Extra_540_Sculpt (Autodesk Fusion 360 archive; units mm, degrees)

design "Extra_540_Sculpt" references "Extra_540_freeform v17_Wings_freestyle", "Extra_540_rear_tags"
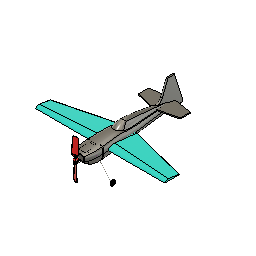
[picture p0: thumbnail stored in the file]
canvas "Canvas1"
canvas "Canvas2"
canvas "Canvas3"
component_insert "Component Insert5"
ground "Ground4"
form "Form2"
sketch "Sketch1" plane through (0, 0, 0) normal (1, 0, 0) x axis (0, 0, -1)
extrude "Extrude1" add sketch "Sketch1" distance 1.5
fillet "Fillet1" radius 1.5
fillet "Fillet2" radius 0.75
form "Form1"
component_insert "Component Insert6"
ground "Ground5"
place_component sketch "Sketch1"
work_plane "WorkPlane1" sketch "Sketch1" AlongDistance 6
sketch "Sketch1" plane through (0, 6, 0) normal (0, 1, 0) x axis (1, 0, 0)
extrude "Extrude1" new body sketch "Sketch1" along normal blind 2
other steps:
create_component "CreateComponent5"
create_component "CreateComponent7"
create_component "CreateComponent8" sketch "Sketch1"

design "Extra_540_freeform_Undercarriage"
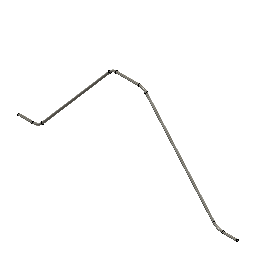
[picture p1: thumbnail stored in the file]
base_feature "Base Feature"
sketch "Path (1)" plane through (0, 0, -48.1) normal (0, 0, 1) x axis (1, 0, 0)
  dimension "d165" = 5
  dimension "d166" = 4
  dimension "d178" = 0
  dimension "d179" = 0
  dimension "d180" = 0
  dimension "d181" = 0
  dimension "d190" = 0
  dimension "d191" = 0
  dimension "d192" = 0
  dimension "d193" = 0
sketch "Profile" plane through (0, 0, 0) normal (1, 0, 0) x axis (0, 0, -1)
  circle C1 centre (47.7, -10.2807) radius 0.375
  dimension "d167" diameter C1 = 0.75
sweep "Sweep1" sketch "Profile" TwistAngle 0 TaperAngle 0

design "Propeller_3_x_1"
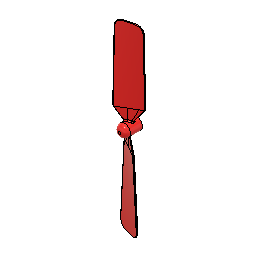
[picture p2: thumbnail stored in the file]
sketch "Sketch1" plane through (0, 0, 0) normal (1, 0, 0) x axis (0, 0, -1)
  dimension "d1" = 1
  dimension "d2" = 2.5
  dimension "d3" = 2
  dimension "d5" = 7
  dimension "d6" = 115
  dimension "d7" = 1.5
revolve "Revolve1" sketch "Sketch1" AlongAngle 360
work_plane "WorkPlane1" AlongDistance 38
sketch "Sketch2" plane through (0, 38, 0) normal (0, 1, 0) x axis (1, 0, 0)
  dimension "d10" = 3
  dimension "d11" = 10
  dimension "d12" = 0.5
  dimension "d13" = 10
work_plane "WorkPlane2" AlongDistance 7
sketch "Sketch3" plane through (0, 7, 0) normal (0, 1, 0) x axis (1, 0, 0)
  dimension "d15" = 10
  dimension "d16" = 0.5
  dimension "d17" = 30
sketch "Sketch4" plane through (0, 0, 0) normal (1, 0, 0) x axis (0, 0, -1)
sweep "Sweep1" sketch "Sketch3" TwistAngle -15 TaperAngle 0
sketch "Sketch5" plane through (0, 0, 0) normal (0, 1, 0) x axis (1, 0, 0)
  dimension "d24" = 0.5
  dimension "d25" = 1
  dimension "d26" = 60
sketch "Sketch6" plane through (0, 0, 0) normal (1, 0, 0) x axis (0, 0, -1)
loft "Loft2" sketch "Sketch5" + "Sketch3"
fillet "Fillet2" radius 3
fillet "Fillet3" radius 2
fillet "Fillet4" radius 0.2
fillet "Fillet5" radius 0.5
circular_pattern "C-Pattern1" TotalAngle 360

design "Extra_540_rear_tags" references "Extra_540_freeform_Undercarriage", "Motor_prop_rear_tags", "Sleeve", "Extra_540_wheel"
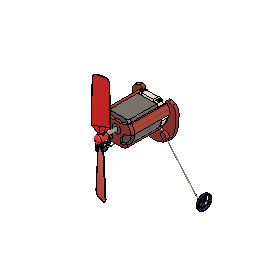
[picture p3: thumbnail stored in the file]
canvas "Canvas1"
canvas "Canvas2"
canvas "Canvas3"
component_insert "Component Insert4"
position "Position2"
base_feature "Base Feature"
work_plane "WorkPlane1" AlongDistance -50.1
sketch "Sketch3" plane through (0, 0, -50.1) normal (0, 0, 1) x axis (1, 0, 0)
extrude "Extrude1" new body sketch "Sketch3" along normal blind 2 taper -5
sketch "Sketch12" plane through (0, 0, -48.1) normal (0, 0, 1) x axis (1, 0, 0)
extrude "Extrude9" cut sketch "Sketch12" no distance stored
sketch "Sketch13" plane through (0, 0, -48.1) normal (0, 0, 1) x axis (1, 0, 0)
  dimension "d100" = 2
  dimension "d104" = 1.5
  dimension "d105" = 6
  dimension "d106" = 12
extrude "Extrude10" add sketch "Sketch13" along normal blind 25
sketch "Sketch14" plane through (0, 0, -23.1) normal (0, 0, 1) x axis (1, 0, 0)
  dimension "d109" = 6.0836
  dimension "d110" = 10
extrude "Extrude11" add sketch "Sketch14" along normal blind 1.5
sketch "Sketch7" plane through (0, 0, -48.1) normal (0, 0, 1) x axis (1, 0, 0)
  dimension "d141" = 4
  dimension "d143" = 4
  dimension "d144" = 2.5
  dimension "d113" = 2
  dimension "d114" = 8
extrude "Extrude5" add sketch "Sketch7" along normal blind 2.5
fillet "Fillet2" radius 1
sketch "Sketch8" plane through (4.0871, 0, 0) normal (1, 0, 0) x axis (0, 0, -1)
sketch "Sketch9" plane through (4.0871, 0, 0) normal (1, 0, 0) x axis (0, 0, -1)
  dimension "d148" = 0.4
  dimension "d149" = 0.8
extrude "Extrude6" cut sketch "Sketch9" to an object
sketch "Sketch10" plane through (0, 0, -48.1) normal (0, 0, 1) x axis (1, 0, 0)
  dimension "d154" = 29.9506
  dimension "d155" = 26.0609
  dimension "d161" = 2.5
  dimension "d162" = 3.5
extrude "Extrude7" add sketch "Sketch10" along normal blind 0.8
sketch "Sketch11" plane through (0, 0, -47.3) normal (0, 0, 1) x axis (1, 0, 0)
  dimension "d164" = 1
extrude "Extrude8" add sketch "Sketch11" along normal blind 1.5
fillet "Fillet3" radius 2
chamfer "Chamfer2" distance 0.5
fillet "Fillet4" radius 1.5
joint "Assemble11" OffsetX 0 OffsetY 0 OffsetZ 0 AngleZ 0 alignAngle 180 alignOffsetX 0 alignOffsetY 0 alignOffsetZ 0
ground "Ground7"
component_insert "Component Insert13"
joint "Assemble12" OffsetX 0 OffsetY 0 OffsetZ 0 AngleZ 0 alignAngle 0 alignOffsetX 0 alignOffsetY 0 alignOffsetZ 0
component_insert "Component Insert14"
joint "Assemble13" OffsetX 0 OffsetY 0 OffsetZ 0 AngleZ 0 OffsetX 0 OffsetY 0 OffsetZ 0 AngleZ 0 alignAngle -90 alignOffsetX 0 alignOffsetY 0 alignOffsetZ 0
component_insert "Component Insert15"
joint "Assemble14" OffsetX 0 OffsetY 0 OffsetZ 0 AngleZ 0 OffsetX 0 OffsetY 0 OffsetZ 0 AngleZ 0 alignAngle -90 alignOffsetX 0 alignOffsetY 0 alignOffsetZ 0
component_insert "Component Insert16"
component_insert "Component Insert17"
joint "Assemble15" OffsetX 0 OffsetY 0 OffsetZ 0 AngleZ 0 OffsetX 0 OffsetY 0 OffsetZ 0 AngleZ 0 alignAngle -90 alignOffsetX 0 alignOffsetY 0 alignOffsetZ 0
joint "Assemble16" OffsetX 0 OffsetY 0 OffsetZ 0 AngleZ 0 OffsetX 0 OffsetY 0 OffsetZ 0 AngleZ 0 alignAngle -90 alignOffsetX 0 alignOffsetY 0 alignOffsetZ 0
component_insert "Component Insert18"
joint "Assemble17" OffsetX 0 OffsetY 0 OffsetZ 0 AngleZ 0 OffsetX 0 OffsetY 0 OffsetZ 0 AngleZ 0 alignAngle 0 alignOffsetX 0 alignOffsetY 0 alignOffsetZ 0
component_insert "Component Insert19"
joint "Assemble18" OffsetX 0 OffsetY 0 OffsetZ 0 AngleZ 0 OffsetX 0 OffsetY 0 OffsetZ 0 AngleZ 0 alignAngle 0 alignOffsetX 0 alignOffsetY 0 alignOffsetZ 0
component_insert "Component Insert6"
joint "Assemble1" OffsetX 0 OffsetY 0 OffsetZ 0 AngleZ 0 alignAngle 0 alignOffsetX 0 alignOffsetY 0 alignOffsetZ 0
joint "Assemble2" OffsetX 0 OffsetY 0 OffsetZ 0 AngleZ 0 alignAngle 0 alignOffsetX 0 alignOffsetY 0 alignOffsetZ 0
component_insert "Component Insert7"
joint "Assemble3" OffsetX 0 OffsetY 0 OffsetZ 0 AngleZ 0 OffsetX 0 OffsetY 0 OffsetZ 0 AngleZ 0 alignAngle -90 alignOffsetX 0 alignOffsetY 0 alignOffsetZ 0
component_insert "Component Insert8"
joint "Assemble4" OffsetX 0 OffsetY 0 OffsetZ 0 AngleZ 0 OffsetX 0 OffsetY 0 OffsetZ 0 AngleZ 0 alignAngle 0 alignOffsetX 0 alignOffsetY 0 alignOffsetZ 0
component_insert "Component Insert9"
joint "Assemble5" OffsetX 0 OffsetY 0 OffsetZ 0 AngleZ 0 OffsetX 0 OffsetY 0 OffsetZ 0 AngleZ 0 alignAngle -90 alignOffsetX 0 alignOffsetY 0 alignOffsetZ 0
component_insert "Component Insert10"
joint "Assemble6" OffsetX 0 OffsetY 0 OffsetZ 0 AngleZ 0 OffsetX 0 OffsetY 0 OffsetZ 0 AngleZ 0 alignAngle -90 alignOffsetX 0 alignOffsetY 0 alignOffsetZ 0
component_insert "Component Insert11"
joint "Assemble7" OffsetX 0 OffsetY 0 OffsetZ 0 AngleZ 0 OffsetX 0 OffsetY 0 OffsetZ 0 AngleZ 0 alignAngle -90 alignOffsetX 0 alignOffsetY 0 alignOffsetZ 0
component_insert "Component Insert12"
joint "Assemble8" OffsetX 0 OffsetY 0 OffsetZ 0 AngleZ 0 OffsetX 0 OffsetY 0 OffsetZ 0 AngleZ 0 alignAngle 0 alignOffsetX 0 alignOffsetY 0 alignOffsetZ 0
ground "Ground4"
ground "Ground5"
position "Position3"
ground "Ground6"
joint "Assemble9" OffsetX 0 OffsetY 0 OffsetZ 0 AngleZ 0 alignAngle 180 alignOffsetX 0 alignOffsetY 0 alignOffsetZ 0
joint "Assemble10" OffsetX 0 OffsetY 0 OffsetZ 0 AngleZ 0 alignAngle 180 alignOffsetX 0 alignOffsetY 0 alignOffsetZ 0
ground "Ground3"
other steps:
create_component "CreateComponent3"
joint_origin "JointOrigin1" OffsetX 0 OffsetY 0 OffsetZ 0 AngleZ 0
joint_origin "JointOrigin2" OffsetX 0 OffsetY 0 OffsetZ 0 AngleZ 0
joint_origin "JointOrigin3" OffsetX 0 OffsetY 0 OffsetZ 0 AngleZ 0
joint_origin "JointOrigin4" OffsetX 0 OffsetY 0 OffsetZ 0 AngleZ 0
joint_origin "JointOrigin5" OffsetX 0 OffsetY 0 OffsetZ 0 AngleZ 0
joint_origin "JointOrigin6" OffsetX 0 OffsetY 0 OffsetZ 0 AngleZ 0

design "Motor_body_rev"
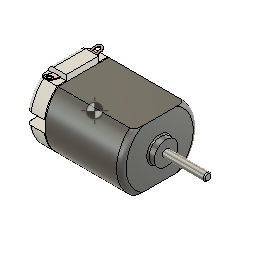
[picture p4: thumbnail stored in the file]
sketch "Sketch1" plane through (0, 0, 0) normal (1, 0, 0) x axis (0, 0, -1)
  dimension "d1" = 20.1
  dimension "d2" = 15.1
extrude "Extrude1" new body sketch "Sketch1" along normal blind 20
sketch "Sketch2" plane through (0, 0, 0) normal (-1, 0, 0) x axis (0, 0, 1)
  dimension "d5" = 1
extrude "Extrude2" add sketch "Sketch2" along normal blind 0.25
sketch "Sketch1"
sketch "Sketch2" plane through (0, 0, 0) normal (1, 0, 0) x axis (0, 0, -1)
work_plane "WorkPlane1"
sketch "Sketch3" plane through (-0.25, 6.55, 6.245) normal (1, 0, 0) x axis (0, 0, -1)
  dimension "d8" = 8.5
  dimension "d9" = 1.4
extrude "Extrude1" new body sketch "Sketch3" against normal blind 4.75
sketch "Sketch4" plane through (-5, 0, 0) normal (-1, 0, 0) x axis (0, 0, 1)
  dimension "d12" = 10
  dimension "d13" = 4
extrude "Extrude2" add sketch "Sketch4" along normal blind 2.3
sketch "Sketch3" plane through (20, 0, 0) normal (1, 0, 0) x axis (0, 0, -1)
  dimension "d16" = 6.15
extrude "Extrude3" add sketch "Sketch3" along normal blind 1.7
sketch "Sketch1" plane through (-7.3, 0, 0) normal (-1, 0, 0) x axis (0, 0, 1)
  dimension "d19" = 2
extrude "Extrude1" new body sketch "Sketch1" along normal blind 2
sketch "Sketch2" plane through (21.7, 0, 0) normal (1, 0, 0) x axis (0, 0, -1)
  circle C1 centre (0, 0) radius 3.075
extrude "Extrude4" cut of existing geometry blind -38
work_plane "WorkPlane1" AlongDistance 2
sketch "Sketch1" plane through (-2, 0, 0) normal (-1, 0, 0) x axis (0, 0, -1)
  dimension "d29" = 3.25
  dimension "d30" = 0.2
  dimension "d31" = 15
extrude "Extrude1" new body sketch "Sketch1" along normal blind 2
fillet "Fillet1" radius 1
sketch "Sketch2" plane through (0, 6.4116, 1.718) normal (0, 0.9659, 0.2588) x axis (1, 0, 0)
  dimension "d36" = 1.5
  dimension "d37" = 0.5
extrude "Extrude2" cut sketch "Sketch2" to an object
sketch "Sketch3" plane through (0, 6.4116, -1.718) normal (0, 0.9659, -0.2588) x axis (-1, 0, 0)
  dimension "d41" = 1.5
  dimension "d42" = 0.5
extrude "Extrude3" cut sketch "Sketch3" to an object
sketch "Sketch5" plane through (-5, 0, 0) normal (-1, 0, 0) x axis (0, 0, 1)
  dimension "d45" = 6
  dimension "d46" = 1
  dimension "d47" = 1
  dimension "d48" = 7
extrude "Extrude4" add sketch "Sketch5" along normal blind 0.1
sketch "Sketch6" plane through (-5, 0, 0) normal (-1, 0, 0) x axis (0, 0, 1)
  dimension "d51" = 3
  dimension "d52" = 4.825
extrude "Extrude5" cut sketch "Sketch6" to an object
fillet "Fillet1" radius 1.25
fillet "Fillet1" radius 1.25
extrude "Extrude3" add of existing geometry blind 40
chamfer "Chamfer1" distance 0.5 rotateAngle 45
fillet "Fillet2" radius 1.4
fillet "Fillet2" radius 0.3
fillet "Fillet1" radius 0.25
ground "Ground1"
joint "Assemble1" alignAngle 0 alignOffsetX 0 alignOffsetY 0 alignOffsetZ 11
move "Move1"
ground "Ground2"
ground "Ground3"
component_from_bodies "Body->Comp"
joint "Assemble5" alignAngle 0 alignOffsetX 0 alignOffsetY 0 alignOffsetZ 0
joint "Assemble6" alignAngle 0 alignOffsetX 0 alignOffsetY 0 alignOffsetZ 0
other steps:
base_feature "Base Feature"
create_component "CreateComponent1"
create_component "CreateComponent2"
extrude "Extrude3" cut of existing geometry blind -38
extrude "Extrude2" cut of existing geometry blind -38
create_component "CreateComponent3"
joint_origin "JointOrigin1" OffsetX 0 OffsetY 0 OffsetZ 0 AngleZ 0
joint_origin "JointOrigin1" OffsetX 0 OffsetY 0 OffsetZ 0 AngleZ 0
create_component "CreateComponent4"
remove_body "RemoveBody1"
joint_origin "JointOrigin3" OffsetX 0 OffsetY 0 OffsetZ 0 AngleZ 0
joint_origin "JointOrigin4" OffsetX 0 OffsetY 0 OffsetZ 0 AngleZ 0
joint_origin "JointOrigin2" OffsetX 0 OffsetY 0 OffsetZ 0 AngleZ 0
joint_origin "JointOrigin5" OffsetX 0 OffsetY 0 OffsetZ 0 AngleZ 0

design "Extra_540_freeform v17_Wings_freestyle"
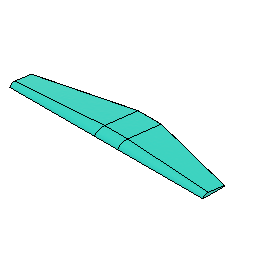
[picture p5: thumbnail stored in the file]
sketch "Sketch1" plane through (0, 0, 0) normal (1, 0, 0) x axis (0, 0, -1)
  dimension "d105" = 1
  dimension "d107" = 2
  dimension "d108" = 61
  dimension "d109" = 56
  dimension "d110" = 6.5
  dimension "d111" = 11
extrude "Extrude1" new body sketch "Sketch1" distance 15
sketch "Sketch4" plane through (0, -2, 0) normal (0, -1, 0) x axis (1, 0, 0)
  dimension "d123" = 110
work_plane "WorkPlane1" AlongDistance 110
sketch "Sketch2" plane through (125, 1.1412, -88.9996) normal (1, 0, 0) x axis (0, 0, -1)
  dimension "d124" = 4
  dimension "d125" = 1
loft "Loft1" sketch "Sketch2"
mirror "Mirror1"

design "Sleeve"
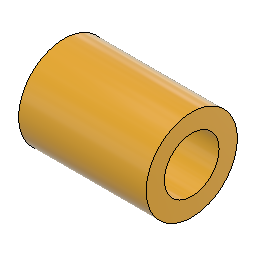
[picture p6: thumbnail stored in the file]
sketch "Sketch1" plane through (0, 0, 0) normal (1, 0, 0) x axis (0, 0, -1)
  circle C1 centre (0, 0) radius 0.375
  circle C2 centre (0, 0) radius 0.625
  dimension "d1" diameter C1 = 0.75
  dimension "d2" diameter C2 = 1.25
extrude "Extrude1" new body sketch "Sketch1" along normal blind 1.75

design "Extra_540_wheel"
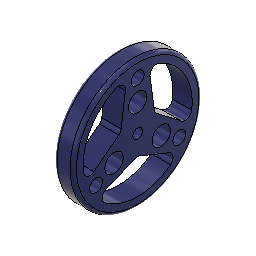
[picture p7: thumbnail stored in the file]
sketch "Sketch1" plane through (0, 0, 0) normal (1, 0, 0) x axis (0, 0, -1)
  dimension "d1" = 0.75
  dimension "d2" = 10
  dimension "d5" = 1
  dimension "d6" = 0.4
  dimension "d7" = 2
extrude "Extrude1" new body sketch "Sketch1" along normal blind 1.5
fillet "Fillet1" radius 0.5
fillet "Fillet2" radius 0.25

design "Motor_prop_rear_tags" references "Propeller_3_x_1", "Motor_body_rev"
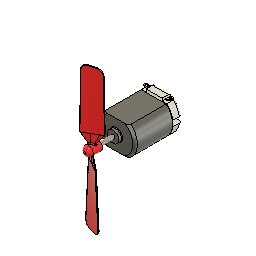
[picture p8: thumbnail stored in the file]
component_insert "Component Insert1"
ground "Ground1"
component_insert "Component Insert2"
joint "Assemble1" OffsetX 0 OffsetY 0 OffsetZ 0 AngleZ 0 OffsetX 0 OffsetY 0 OffsetZ 0 AngleZ 0 alignAngle 180 alignOffsetX 0 alignOffsetY 0 alignOffsetZ 3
